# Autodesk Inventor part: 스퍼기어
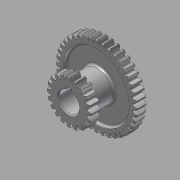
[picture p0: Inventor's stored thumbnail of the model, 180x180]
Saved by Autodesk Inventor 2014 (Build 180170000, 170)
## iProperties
Created: 2015-09
Part Number: 스퍼기어
Material: 강철, 연강
Document SubType Name: Modeling
Designer: mduedu
Density: 1 g/cm^3
Appearance: 강철
Author: mduedu
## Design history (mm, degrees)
sketch "스케치1"
  geometry: C1 r 38 at (0, 0); C2 r 40 at (0, 0); C3 r 35.5 at (0, 0); 1 further point
  constraints: 3 centre point, 3 coincident
  dimensions: "d0" = 76 diameter of C1; "d2" = 2 radial gap between concentric circles of C2 C1; "d3" = 71 diameter of C3 (computed from d0)
extrude "돌출1" new body sketch "스케치1" stored distance "d4" = 10; taper "d5" = 0 deg
sketch "스케치2"
  geometry: L1 (0, 35.5)-(0, -35.5); L2 (0, 0)-(40, 0); L3 (0, 0.57)-(39.996, 0.57); L4 (0, 1.57)-(39.969, 1.57); L5 (0, 2.07)-(39.946, 2.07); A1 r 35.5 centre (0, 0) between (0, 35.5) and (0, -35.5) reference; A2 r 40 centre (0, 0) between (40, 0) and (39.946, 2.07) reference; A3 r 9.234 centre (34.93, -7.149) between (39.996, 0.57) and (35.44, 2.07); A4 r 9.234 centre (34.93, 7.149) between (35.44, -2.07) and (39.996, -0.57); A5 r 40 centre (0, 0) between (39.996, -0.57) and (39.996, 0.57); A6 r 35.5 centre (0, 0) between (35.44, -2.07) and (35.44, 2.07); 4 further points
  constraints: 16 point on circle, 10 end point, 6 point on line, 4 centre point, 3 coincident, 3 parallel, 3 symmetric about line, 2 midpoint, 1 perpendicular, 1 vertical, 3 other
  dimensions: "d6" = 0.5 distance between parallel lines of L4 L5; "d8" = 1 distance between parallel lines of L3 L4; "d9" = 1.57 distance between parallel lines of L2 L4
extrude "돌출2" join sketch "스케치2" distance "d10" = 5; taper "d12" = 0 deg; dims "d11" = 5, "d13" = 0
fillet "모깎기1" dims "d17" = 0.5
chamfer "모따기1" distance "d21" = 1; stored, may be unused: second distance "d22" = 2, angle "d23" = 45 deg
sketch "스케치3"
  geometry: C1 r 32.5 at (0, 0); C2 r 15 at (0, 0); 1 further point
  constraints: 2 centre point, 2 coincident
  dimensions: "d27" = 65 diameter of C1; "d28" = 30 diameter of C2
extrude "돌출3" cut sketch "스케치3" distance "d29" = 3; taper "d30" = 0 deg
fillet "모깎기2" dims "d31" = 2
node "작업 평면2"
  node "작업 평면1"
sketch "스케치4"
  geometry: C1 r 15 at (0, 0) reference; 1 further point
extrude "돌출4" join sketch "스케치4" stored distance "d34" = 3; taper "d35" = 0 deg
sketch "스케치5"
  geometry: C1 r 17.5 at (0, 0); C2 r 20 at (0, 0); C3 r 22 at (0, 0); 1 further point
  constraints: 3 centre point, 3 coincident
  dimensions: "d36" = 40 diameter of C2; "d38" = 2 radial gap between concentric circles of C2 C3; "d39" = 35 diameter of C1 (= d36 - 2.5 x d38)
extrude "돌출6" join sketch "스케치5" distance "d46" = 10; taper "d47" = 0 deg
sketch "스케치6"
  geometry: L1 (0, 0)-(0, 22); L2 (-17.5, 0)-(17.5, 0); L3 (-0.57, 0)-(-0.57, 21.993); L4 (-1.57, 0)-(-1.57, 21.944); L5 (-2.07, 0)-(-2.07, 21.902); A1 r 22 centre (0, 0) between (0, 22) and (-0.57, 21.993) reference; A2 r 17.5 centre (0, 0) between (-17.5, 0) and (17.5, 0) reference; A3 r 9.431 centre (7.348, 16.868) between (-0.57, 21.993) and (-2.07, 17.377); A4 r 9.431 centre (-7.348, 16.868) between (2.07, 17.377) and (0.57, 21.993); A5 r 17.5 centre (0, 0) between (2.07, 17.377) and (-2.07, 17.377); A6 r 22 centre (0, 0) between (0.57, 21.993) and (-0.57, 21.993); 4 further points
  constraints: 16 point on circle, 10 end point, 5 point on line, 4 centre point, 3 coincident, 3 symmetric about line, 2 parallel, 2 perpendicular, 1 midpoint, 1 vertical, 3 other
  dimensions: "d40" = 0.5 distance between parallel lines of L4 L5; "d42" = 1 distance between parallel lines of L3 L4; "d43" = 1.57 distance between parallel lines of L1 L4
extrude "돌출5" join sketch "스케치6" distance "d44" = 10; taper "d45" = 0 deg
fillet "모깎기3" dims "d48" = 0.5
chamfer "모따기2" distance "d49" = 1; stored, may be unused: second distance "d50" = 2, angle "d51" = 45 deg
sketch "스케치7"
  geometry: C1 r 10 at (0, 0); 1 further point
  constraints: 1 centre point, 1 coincident
  dimensions: "d55" = 20 diameter of C1
extrude "돌출7" cut sketch "스케치7" stored distance "d56" = 10; taper "d57" = 0 deg
sketch "스케치8"
  geometry: L1 (-9.539, -3)-(-12.8, -3); L2 (-12.8, -3)-(-12.8, 3); L3 (-12.8, 3)-(-9.539, 3); L4 (-9.539, 3)-(-9.539, -3); A1 r 10 centre (0, 0) between (-9.539, -3) and (-9.539, 3) reference; 2 further points
  constraints: 8 end point, 3 point on circle, 2 parallel, 1 horizontal, 1 horizontal alignment, 1 perpendicular
  dimensions: "d58" = 6 distance of L1.end L2.end; "d60" = 22.8 distance from line of point (10, 0) L2
extrude "돌출8" cut sketch "스케치8" stored distance "d61" = 10; taper "d62" = 0 deg
chamfer "모따기3" distance "d63" = 1; stored, may be unused: second distance "d64" = 2, angle "d65" = 45 deg
fillet "모깎기4" dims "d66" = 2
node "솔리드1"
pattern_circular "원형 패턴3" dims "d25" = 360 deg
mirror "대칭1"
pattern_circular "원형 패턴4" dims "d53" = 360 deg
other parameters: "d32" = 5, "d33" = 42
